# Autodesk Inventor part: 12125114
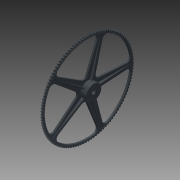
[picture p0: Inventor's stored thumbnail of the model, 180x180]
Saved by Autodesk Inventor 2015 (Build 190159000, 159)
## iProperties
Created: 2018-06
Part Number: 12125114
Material: Ferro, Ghisa grigia ASTM A48 Grado 20
Document SubType Name: Modeling
Designer: stagistacad
Density: 7.3953 g/cm^3
Appearance: Grigio ferro
Author: stagistacad
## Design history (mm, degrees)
sketch "Schizzo1"
  geometry: L1 (-25.14, 911.712)-(-24.765, 911.712); L2 (-22.765, 909.712)-(-22.765, 546.445); L3 (-24.765, 544.445)-(-25.14, 544.445); L4 (-3.14, 911.712)-(-3.515, 911.712); L5 (-3.515, 544.445)-(-3.14, 544.445); L6 (-19.54, 935.91)-(-8.74, 935.91); L7 (-5.515, 546.445)-(-5.515, 909.712); L8 (-22.24, 922.41)-(-22.24, 924.41); L9 (-3.14, 394.445)-(-3.14, 21.945); L10 (-6.04, 924.41)-(-6.04, 922.41); L11 (-22.24, 16.48)-(-22.24, 14.48); L12 (-6.04, 14.48)-(-6.04, 16.48); L13 (-19.54, 2.98)-(-8.74, 2.98); L14 (-22.765, 29.179)-(-22.765, 392.445); L15 (-24.765, 394.445)-(-25.14, 394.445); L16 (-25.14, 27.179)-(-24.765, 27.179); L17 (-5.515, 392.445)-(-5.515, 29.179); L18 (-3.515, 394.445)-(-3.14, 394.445); L19 (-3.14, 27.179)-(-3.515, 27.179); L20 (-22.765, 33.102)-(-5.515, 33.102); L21 (-22.765, 388.523)-(-5.515, 388.523); L22 (-5.515, 909.712)-(19.157, 544.445); L23 (-22.24, 922.41)-(-6.04, 922.41); L24 (-22.24, 16.48)-(-6.04, 16.48); L25 (-22.24, 922.41)-(-22.24, 916.945); L26 (-6.04, 922.41)-(-6.04, 916.945); L27 (-6.04, 916.945)-(-3.14, 916.945); L28 (-6.04, 21.945)-(-3.14, 21.945); L29 (-3.14, 916.945)-(-3.14, 874.55); L30 (-25.14, 916.945)-(-22.24, 916.945); L31 (-25.14, 21.945)-(-22.24, 21.945); L32 (-25.14, 916.945)-(-25.14, 21.945); L33 (-3.14, 544.445)-(52.86, 544.445); L34 (-3.14, 394.445)-(52.86, 394.445); L35 (54.86, 542.445)-(54.86, 396.445); L36 (-23.64, 488.945)-(53.36, 488.945); L37 (-23.64, 449.945)-(53.36, 449.945); L38 (-25.14, 490.445)-(-25.14, 448.445); L39 (54.86, 490.445)-(54.86, 448.445); L40 (-23.64, 488.945)-(-23.64, 449.945); L41 (-23.64, 488.945)-(-25.14, 490.445); L42 (-23.64, 449.945)-(-25.14, 448.445); L43 (53.36, 488.945)-(53.36, 449.945); L44 (53.36, 488.945)-(54.86, 490.445); L45 (53.36, 449.945)-(54.86, 448.445); L46 (-6.04, 21.945)-(-6.04, 16.48); L47 (-22.24, 21.945)-(-22.24, 16.48); L48 (-42.64, 469.445)-(72.36, 469.445); A1 r 2 centre (-24.765, 546.445) between (-24.765, 544.445) and (-22.765, 546.445); A2 r 2 centre (-24.765, 909.712) between (-22.765, 909.712) and (-24.765, 911.712); A3 r 2 centre (-3.515, 546.445) between (-5.515, 546.445) and (-3.515, 544.445); A4 r 2 centre (-3.515, 909.712) between (-3.515, 911.712) and (-5.515, 909.712); A5 r 25.4 centre (3.16, 924.514) between (-19.54, 935.91) and (-22.24, 924.41); A6 r 25.4 centre (-31.44, 924.514) between (-6.04, 924.41) and (-8.74, 935.91); A7 r 25.4 centre (-31.44, 14.377) between (-8.74, 2.98) and (-6.04, 14.48); A8 r 25.4 centre (3.16, 14.377) between (-22.24, 14.48) and (-19.54, 2.98); A9 r 2 centre (-24.765, 392.445) between (-22.765, 392.445) and (-24.765, 394.445); A10 r 2 centre (-24.765, 29.179) between (-24.765, 27.179) and (-22.765, 29.179); A11 r 2 centre (-3.515, 392.445) between (-3.515, 394.445) and (-5.515, 392.445); A12 r 2 centre (-3.515, 29.179) between (-5.515, 29.179) and (-3.515, 27.179); A13 r 2 centre (52.86, 542.445) between (54.86, 542.445) and (52.86, 544.445); A14 r 2 centre (52.86, 396.445) between (52.86, 394.445) and (54.86, 396.445); 1 further point
  constraints: 96 end point, 28 point on circle, 16 point on line, 14 centre point
revolve "Rivoluzione1" sketch "Schizzo1" stored, may be unused: angle "d0" = 90 deg
sketch "Schizzo2"
  geometry: L1 (5.049, 74.83)-(5.049, 442.238); L2 (-5.049, 74.83)-(-5.049, 442.238); L3 (36.953, -59.452)-(42.661, -67.308); L4 (-377.522, 94.013)-(-121.912, -7.207); L5 (-69.607, 27.926)-(-419.033, 141.461); L6 (-72.728, 18.321)-(-422.153, 131.857); L7 (-48.069, -57.571)-(-264.026, -354.81); L8 (-39.899, -63.507)-(-255.856, -360.746); L9 (39.899, -63.507)-(42.661, -67.308); L10 (42.661, -132.485)-(30.819, -118.172); L11 (-206.072, -329.994)-(-30.819, -118.172); L12 (27.249, 388.097)-(42.661, 143.356); L13 (-360.681, 145.844)-(-94.393, 77.488); L14 (-27.249, 388.097)-(-44.527, 113.719); L15 (-250.163, -297.96)-(-102.865, -65.828); L16 (0, 0)-(0, 477.965); L17 (0, 0)-(-477.965, 0); L18 (0, 0)-(0, -477.965); C1 r 75 at (0, 0) reference; C2 r 19.5 at (0, 0); C3 r 21 at (0, 0); A1 r 452.965 centre (0, 0) between (42.661, 450.952) and (42.661, -450.952); A2 r 447.5 centre (0, 0) between (42.661, 445.462) and (42.661, -445.462); A3 r 40 centre (-392.249, 56.823) between (-377.522, 94.013) and (-431.836, 62.557); A4 r 436.344 centre (0, 0) between (-431.836, 62.557) and (-312.593, -304.437); A5 r 466.465 centre (0, 0) between (42.661, 464.51) and (42.661, -464.51); A6 r 442.266 centre (0, 0) between (42.661, 440.204) and (42.661, -440.204); A7 r 436.344 centre (0, 0) between (-192.94, -391.369) and (42.661, -434.253); A8 r 40 centre (-175.253, -355.492) between (-206.072, -329.994) and (-192.94, -391.369); A9 r 40 centre (0, -143.671) between (30.819, -118.172) and (-30.819, -118.172); A10 r 40 centre (67.17, 390.611) between (42.661, 422.222) and (27.249, 388.097); A11 r 40 centre (-84.448, 116.232) between (-94.393, 77.488) and (-44.527, 113.719); A12 r 40 centre (-350.736, 184.588) between (-386.133, 203.217) and (-360.681, 145.844); A13 r 40 centre (-67.17, 390.611) between (-27.249, 388.097) and (-73.949, 430.032); A14 r 436.344 centre (0, 0) between (-73.949, 430.032) and (-386.133, 203.217); A15 r 40 centre (-136.639, -44.397) between (-102.865, -65.828) and (-121.912, -7.207); A16 r 40 centre (-283.937, -276.529) between (-312.593, -304.437) and (-250.163, -297.96); 4 further points
  constraints: 38 point on circle, 36 end point, 18 centre point, 1 point on line, 11 other
extrude "Estrusione1" cut sketch "Schizzo2" distance "d1" = 100; taper "d2" = 0 deg
pattern_circular "Serie circolare1" dims angle "d4" = 360 deg
sketch "Schizzo3"
  geometry: L1 (5.049, 74.83)-(5.049, 442.238); L2 (-5.049, 74.83)-(-5.049, 442.238); L3 (36.953, -59.452)-(42.661, -67.308); L4 (-377.522, 94.013)-(-121.912, -7.207); L5 (-69.607, 27.926)-(-419.033, 141.461); L6 (-72.728, 18.321)-(-422.153, 131.857); L7 (-48.069, -57.571)-(-264.026, -354.81); L8 (-39.899, -63.507)-(-255.856, -360.746); L9 (39.899, -63.507)-(42.661, -67.308); L10 (42.661, -132.485)-(30.819, -118.172); L11 (-206.072, -329.994)-(-30.819, -118.172); L12 (27.249, 388.097)-(42.661, 143.356); L13 (-360.681, 145.844)-(-94.393, 77.488); L14 (-27.249, 388.097)-(-44.527, 113.719); L15 (-250.163, -297.96)-(-102.865, -65.828); L16 (0, 0)-(0, 477.965); L17 (0, 0)-(-477.965, 0); L18 (0, 0)-(0, -477.965); C1 r 77 at (0, 0) reference; C2 r 19.5 at (0, 0); C3 r 21 at (0, 0); A1 r 452.965 centre (0, 0) between (42.661, 450.952) and (42.661, -450.952); A2 r 447.5 centre (0, 0) between (42.661, 445.462) and (42.661, -445.462); A3 r 40 centre (-392.249, 56.823) between (-377.522, 94.013) and (-431.836, 62.557); A4 r 436.344 centre (0, 0) between (-431.836, 62.557) and (-312.593, -304.437); A5 r 466.465 centre (0, 0) between (42.661, 464.51) and (42.661, -464.51); A6 r 442.266 centre (0, 0) between (42.661, 440.204) and (42.661, -440.204); A7 r 436.344 centre (0, 0) between (-192.94, -391.369) and (42.661, -434.253); A8 r 40 centre (-175.253, -355.492) between (-206.072, -329.994) and (-192.94, -391.369); A9 r 40 centre (0, -143.671) between (30.819, -118.172) and (-30.819, -118.172); A10 r 40 centre (67.17, 390.611) between (42.661, 422.222) and (27.249, 388.097); A11 r 40 centre (-84.448, 116.232) between (-94.393, 77.488) and (-44.527, 113.719); A12 r 40 centre (-350.736, 184.588) between (-386.133, 203.217) and (-360.681, 145.844); A13 r 40 centre (-67.17, 390.611) between (-27.249, 388.097) and (-73.949, 430.032); A14 r 436.344 centre (0, 0) between (-73.949, 430.032) and (-386.133, 203.217); A15 r 40 centre (-136.639, -44.397) between (-102.865, -65.828) and (-121.912, -7.207); A16 r 40 centre (-283.937, -276.529) between (-312.593, -304.437) and (-250.163, -297.96); 4 further points
  constraints: 38 point on circle, 36 end point, 18 centre point, 1 point on line, 11 other
extrude "Estrusione2" cut sketch "Schizzo3" distance "d6" = 60.38; taper "d7" = 0 deg
pattern_circular "Serie circolare2" dims angle "d9" = 360 deg
fillet "Raccordo1" dims "d11" = 1.9986
sketch "Schizzo4"
  geometry: L1 (-25.378, -488.694)-(25.378, 488.694); L2 (488.694, -25.378)-(-488.694, 25.378); L3 (-12.25, -12.25)-(12.25, 12.25); L4 (-12.25, 12.25)-(12.25, -12.25); C1 r 75 at (0, 0) reference; C2 r 21 at (0, 0) reference; C3 r 5 at (0, 0); C4 r 452.967 at (0, 0); C5 r 1 at (0, 0); C6 r 12.25 at (0, 0); C7 r 6.125 at (0, 0); A1 r 468.352 centre (0, 0) between (-307.689, 353.102) and (-309.77, 351.279); A2 r 221.05 centre (244.281, 362.918) between (48.643, 465.82) and (43.855, 456.151); A3 r 468.352 centre (0, 0) between (25.671, 467.648) and (22.908, 467.792); A4 r 221.05 centre (-183.784, 396.996) between (28.869, 457.344) and (25.671, 467.648); A5 r 8.019 centre (11.213, 460.85) between (3.631, 458.239) and (18.66, 457.874); A6 r 221.05 centre (223.917, 375.824) between (22.908, 467.792) and (18.66, 457.874); A7 r 468.352 centre (0, 0) between (-0.13, 468.352) and (-2.896, 468.343); A8 r 221.05 centre (-205.375, 386.269) between (3.631, 458.239) and (-0.13, 468.352); A9 r 8.019 centre (-14.191, 460.768) between (-21.618, 457.744) and (-6.592, 458.206); A10 r 221.05 centre (202.874, 387.588) between (-2.896, 468.343) and (-6.592, 458.206); A11 r 468.352 centre (0, 0) between (-25.93, 467.634) and (-28.692, 467.473); A12 r 221.05 centre (-226.341, 374.369) between (-21.618, 457.744) and (-25.93, 467.634); A13 r 8.019 centre (-39.552, 459.287) between (-46.801, 455.858) and (-31.823, 457.147); A14 r 221.05 centre (181.215, 398.176) between (-28.692, 467.473) and (-31.823, 457.147); A15 r 468.352 centre (0, 0) between (-51.652, 465.495) and (-54.401, 465.182); A16 r 221.05 centre (-246.621, 361.332) between (-46.801, 455.858) and (-51.652, 465.495); A17 r 8.019 centre (-64.793, 456.411) between (-71.843, 452.587) and (-56.958, 454.7); A18 r 221.05 centre (159.005, 407.554) between (-54.401, 465.182) and (-56.958, 454.7); A19 r 468.352 centre (0, 0) between (-77.217, 461.943) and (-79.944, 461.479); A20 r 221.05 centre (-266.151, 347.198) between (-71.843, 452.587) and (-77.217, 461.943); A21 r 8.019 centre (-89.837, 452.148) between (-96.665, 447.942) and (-81.92, 450.872); A22 r 221.05 centre (136.312, 415.694) between (-79.944, 461.479) and (-81.92, 450.872); A23 r 468.352 centre (0, 0) between (-102.547, 456.988) and (-105.244, 456.374); A24 r 221.05 centre (-284.874, 332.009) between (-96.665, 447.942) and (-102.547, 456.988); A25 r 8.019 centre (-114.609, 446.513) between (-121.195, 441.937) and (-106.633, 445.675); A26 r 221.05 centre (113.206, 422.572) between (-105.244, 456.374) and (-106.633, 445.675); A27 r 468.352 centre (0, 0) between (-127.566, 450.645) and (-130.225, 449.884); A28 r 221.05 centre (-302.731, 315.811) between (-121.195, 441.937) and (-127.566, 450.645); A29 r 8.019 centre (-139.032, 439.521) between (-145.356, 434.59) and (-131.023, 439.124); A30 r 221.05 centre (89.755, 428.167) between (-130.225, 449.884) and (-131.023, 439.124); A31 r 468.352 centre (0, 0) between (-152.197, 442.933) and (-154.81, 442.027); A32 r 221.05 centre (-319.668, 298.655) between (-145.356, 434.59) and (-152.197, 442.933); A33 r 8.019 centre (-163.033, 431.195) between (-169.076, 425.922) and (-155.014, 431.239); A34 r 221.05 centre (66.032, 432.461) between (-154.81, 442.027) and (-155.014, 431.239); A35 r 468.352 centre (0, 0) between (-176.366, 433.877) and (-178.926, 432.827); A36 r 221.05 centre (-335.635, 280.592) between (-169.076, 425.922) and (-176.366, 433.877); A37 r 8.019 centre (-186.539, 421.559) between (-192.282, 415.962) and (-178.535, 422.045); A38 r 221.05 centre (42.109, 435.442) between (-178.926, 432.827) and (-178.535, 422.045); A39 r 468.352 centre (0, 0) between (-199.999, 423.502) and (-202.497, 422.314); A40 r 221.05 centre (-350.583, 261.676) between (-192.282, 415.962) and (-199.999, 423.502); A41 r 8.019 centre (-209.479, 410.643) between (-214.905, 404.738) and (-201.513, 411.569); A42 r 221.05 centre (18.057, 437.1) between (-202.497, 422.314) and (-201.513, 411.569); A43 r 468.352 centre (0, 0) between (-223.026, 411.842) and (-225.454, 410.517); A44 r 221.05 centre (-364.465, 241.966) between (-214.905, 404.738) and (-223.026, 411.842); A45 r 8.019 centre (-231.782, 398.479) between (-236.874, 392.284) and (-223.88, 399.843); A46 r 221.05 centre (-6.049, 437.431) between (-225.454, 410.517) and (-223.88, 399.843); A47 r 468.352 centre (0, 0) between (-245.374, 398.93) and (-247.726, 397.474); A48 r 221.05 centre (-377.241, 221.521) between (-236.874, 392.284) and (-245.374, 398.93); A49 r 8.019 centre (-253.382, 385.106) between (-258.125, 378.64) and (-245.566, 386.903); A50 r 221.05 centre (-30.137, 436.434) between (-247.726, 397.474) and (-245.566, 386.903); A51 r 468.352 centre (0, 0) between (-266.978, 384.807) and (-269.246, 383.224); A52 r 221.05 centre (-388.872, 200.403) between (-258.125, 378.64) and (-266.978, 384.807); A53 r 8.019 centre (-274.211, 370.563) between (-278.591, 363.845) and (-266.507, 372.788); A54 r 221.05 centre (-54.134, 434.111) between (-269.246, 383.224) and (-266.507, 372.788); A55 r 468.352 centre (0, 0) between (-287.771, 369.516) and (-289.948, 367.81); A56 r 221.05 centre (-399.321, 178.677) between (-278.591, 363.845) and (-287.771, 369.516); A57 r 8.019 centre (-294.208, 354.895) between (-298.212, 347.946) and (-286.638, 357.54); A58 r 221.05 centre (-77.966, 430.47) between (-289.948, 367.81) and (-286.638, 357.54); A59 r 8.019 centre (-460.366, 23.907) between (-457.965, 16.256) and (-457.186, 31.269); A60 r 221.05 centre (-408.558, 156.408) between (-298.212, 347.946) and (-307.689, 353.102); A61 r 8.019 centre (-313.312, 338.148) between (-316.926, 330.99) and (-305.899, 341.207); A62 r 221.05 centre (-101.561, 425.521) between (-309.77, 351.279) and (-305.899, 341.207); A63 r 468.352 centre (0, 0) between (-326.674, 335.616) and (-328.651, 333.681); A64 r 221.05 centre (-416.553, 133.664) between (-316.926, 330.99) and (-326.674, 335.616)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; 2 further points
  constraints: 912 point on circle, 461 centre point, 8 end point, 1 coincident, 3 other
extrude "Estrusione3" cut sketch "Schizzo4" stored distance "d12" = 60.38; taper "d13" = 0 deg
node "Solido1"
node "Linea chiusa proiettata1"
